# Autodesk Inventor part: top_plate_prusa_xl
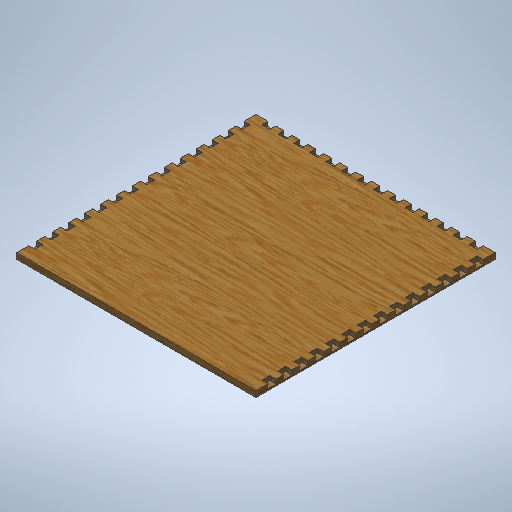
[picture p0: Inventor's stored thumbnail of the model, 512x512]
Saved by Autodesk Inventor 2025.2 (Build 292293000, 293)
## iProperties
Created: 2024-11
Part Number: top_plate_prusa_xl
Material: Plywood, Finish
Document SubType Name: Modeling
Designer: BennF
Density: 0.552 g/cm^3
Appearance: Plywood - New
Author: BennF
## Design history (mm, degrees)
sketch "Sketch2"
  geometry: L1 (-360, 360)-(360, 360); L2 (360, 360)-(360, -360); L3 (360, -360)-(-360, -360); L4 (-360, -360)-(-360, 360); 3 further points
  constraints: 8 end point, 2 midpoint, 2 parallel, 1 horizontal, 1 horizontal alignment, 1 perpendicular, 1 vertical alignment
  dimensions: "d0" = 720 distance of L1.start L1.end (= prusa_xl_width); "d1" = 720 distance of L3.end L1.start (= prusa_xl_depth)
extrude "base_material" new body sketch "Sketch2" distance "d2" = 18 (= thickness); taper "d3" = 0 deg
sketch "Sketch3"
  geometry: L1 (-324, 360)-(-324, 341.8); L2 (-324, 341.8)-(-300, 341.8); L3 (-300, 341.8)-(-300, 360); L4 (-276, 360)-(-276, 341.8); L5 (-276, 341.8)-(-252, 341.8); L6 (-252, 341.8)-(-252, 360); L7 (-228, 360)-(-228, 341.8); L8 (-228, 341.8)-(-204, 341.8); L9 (-204, 341.8)-(-204, 360); L10 (-180, 360)-(-180, 341.8); L11 (-180, 341.8)-(-156, 341.8); L12 (-156, 341.8)-(-156, 360); L13 (-132, 360)-(-132, 341.8); L14 (-132, 341.8)-(-108, 341.8); L15 (-108, 341.8)-(-108, 360); L16 (-84, 360)-(-84, 341.8); L17 (-84, 341.8)-(-60, 341.8); L18 (-60, 341.8)-(-60, 360); L19 (-36, 360)-(-36, 341.8); L20 (-36, 341.8)-(-12, 341.8); L21 (-12, 341.8)-(-12, 360); L22 (12, 360)-(12, 341.8); L23 (12, 341.8)-(36, 341.8); L24 (36, 341.8)-(36, 360); L25 (60, 360)-(60, 341.8); L26 (60, 341.8)-(84, 341.8); L27 (84, 341.8)-(84, 360); L28 (108, 360)-(108, 341.8); L29 (108, 341.8)-(132, 341.8); L30 (132, 341.8)-(132, 360); L31 (156, 360)-(156, 341.8); L32 (156, 341.8)-(180, 341.8); L33 (180, 341.8)-(180, 360); L34 (204, 360)-(204, 341.8); L35 (204, 341.8)-(228, 341.8); L36 (228, 341.8)-(228, 360); L37 (252, 360)-(252, 341.8); L38 (252, 341.8)-(276, 341.8); L39 (276, 341.8)-(276, 360); L40 (300, 360)-(300, 341.8); L41 (300, 341.8)-(324, 341.8); L42 (324, 341.8)-(324, 360); L43 (-360, -324)-(-341.8, -324); L44 (-341.8, -324)-(-341.8, -300); L45 (-341.8, -300)-(-360, -300); L46 (-341.8, -252)-(-360, -252); L47 (-341.8, -276)-(-341.8, -252); L48 (-360, -276)-(-341.8, -276); L49 (-341.8, -204)-(-360, -204); L50 (-341.8, -228)-(-341.8, -204); L51 (-360, -228)-(-341.8, -228); L52 (-341.8, -156)-(-360, -156); L53 (-341.8, -180)-(-341.8, -156); L54 (-360, -180)-(-341.8, -180); L55 (-341.8, -108)-(-360, -108); L56 (-341.8, -132)-(-341.8, -108); L57 (-360, -132)-(-341.8, -132); L58 (-341.8, -60)-(-360, -60); L59 (-341.8, -84)-(-341.8, -60); L60 (-360, -84)-(-341.8, -84); L61 (-341.8, -12)-(-360, -12); L62 (-341.8, -36)-(-341.8, -12); L63 (-360, -36)-(-341.8, -36); L64 (-341.8, 36)-(-360, 36)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; 81 further points
  constraints: 252 end point, 104 vertical alignment, 78 parallel, 53 horizontal alignment, 39 collinear, 6 perpendicular, 2 equal length, 2 horizontal, 1 vertical, 9 other
  dimensions: "d4" = 24 distance of L1.end L2.end (= finger_width); "d5" = 18.2 distance of L2.end L3.end (derived); "d8" = 48 distance of L1.start L4.start (= finger_distance); "d13" = 24 distance of L43.end L44.end (= finger_width); "d14" = 18.2 distance of L44.end L45.end (derived); "d17" = 48 distance of L45.end L46.end (= finger_distance); "d48" = 36 distance between parallel lines of L85 L43 (derived); "d49" = 36 dimension on L1 (derived); "d52" = 48 distance of L86.start L89.start (derived)
extrude "joints" cut sketch "Sketch3" distance "d22" = 13.5 (derived); taper "d23" = 0 deg
sketch "Sketch4" dims "d24" = 6 (= dogbone_diameter)
  geometry: L1 (-341.8, -228)-(-360, -228) reference; L2 (-360, -228)-(-360, -252) reference; L3 (-360, -252)-(-341.8, -252) reference; L4 (-341.8, -252)-(-341.8, -276) reference; L5 (-341.8, -276)-(-360, -276) reference; L6 (-360, -276)-(-360, -300) reference; L7 (-360, -300)-(-341.8, -300) reference; L8 (-341.8, -300)-(-341.8, -324) reference; L9 (-341.8, -324)-(-360, -324) reference; L10 (-360, -324)-(-360, -360) reference; L11 (-360, -360)-(360, -360) reference; L12 (360, -360)-(360, -324) reference; L13 (360, 360)-(324, 360) reference; L14 (132, 360)-(132, 341.8) reference; L15 (132, 341.8)-(108, 341.8) reference; L16 (108, 341.8)-(108, 360) reference; L17 (108, 360)-(84, 360) reference; L18 (84, 360)-(84, 341.8) reference; L19 (84, 341.8)-(60, 341.8) reference; L20 (60, 341.8)-(60, 360) reference; L21 (60, 360)-(36, 360) reference; L22 (36, 360)-(36, 341.8) reference; L23 (36, 341.8)-(12, 341.8) reference; L24 (12, 341.8)-(12, 360) reference; L25 (12, 360)-(-12, 360) reference; L26 (-12, 360)-(-12, 341.8) reference; L27 (-12, 341.8)-(-36, 341.8) reference; L28 (-36, 341.8)-(-36, 360) reference; L29 (-36, 360)-(-60, 360) reference; L30 (-60, 360)-(-60, 341.8) reference; L31 (-60, 341.8)-(-84, 341.8) reference; L32 (-84, 341.8)-(-84, 360) reference; L33 (-84, 360)-(-108, 360) reference; L34 (-108, 360)-(-108, 341.8) reference; L35 (-108, 341.8)-(-132, 341.8) reference; L36 (-132, 341.8)-(-132, 360) reference; L37 (-132, 360)-(-156, 360) reference; L38 (-156, 360)-(-156, 341.8) reference; L39 (-156, 341.8)-(-180, 341.8) reference; L40 (-180, 341.8)-(-180, 360) reference; L41 (-180, 360)-(-204, 360) reference; L42 (-204, 360)-(-204, 341.8) reference; L43 (-204, 341.8)-(-228, 341.8) reference; L44 (-228, 341.8)-(-228, 360) reference; L45 (-228, 360)-(-252, 360) reference; L46 (-252, 360)-(-252, 341.8) reference; L47 (-252, 341.8)-(-276, 341.8) reference; L48 (-276, 341.8)-(-276, 360) reference; L49 (-276, 360)-(-300, 360) reference; L50 (-300, 360)-(-300, 341.8) reference; L51 (-300, 341.8)-(-324, 341.8) reference; L52 (-324, 341.8)-(-324, 360) reference; L53 (-324, 360)-(-360, 360) reference; L54 (-360, 360)-(-360, 324) reference; L55 (-360, 324)-(-341.8, 324) reference; L56 (-341.8, 324)-(-341.8, 300) reference; L57 (-341.8, 300)-(-360, 300) reference; L58 (-360, 300)-(-360, 276) reference; L59 (-360, 276)-(-341.8, 276) reference; L60 (-341.8, 276)-(-341.8, 252) reference; L61 (-341.8, 252)-(-360, 252) reference; L62 (-360, 252)-(-360, 228) reference; L63 (-360, 228)-(-341.8, 228) reference; L64 (-341.8, 228)-(-341.8, 204) reference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; 140 further points
  constraints: 116 end point, 58 point on line, 54 vertical, 27 horizontal, 3 midpoint, 3 perpendicular, 2 horizontal alignment, 1 vertical alignment, 512 other
  dimensions: "d27" = 48 distance of L7.end L104.start (= finger_distance); "d34" = 48 distance of L50.end L133.end (= finger_distance); "d59" = 48 distance of point (343.921, -302.121) point (343.921, -254.121) (derived)
extrude "dogbones" cut sketch "Sketch4" distance "d39" = 13.5 (derived); taper "d40" = 0 deg
body "Solid1"
node "Sketch Rectangular Pattern1" dims "d8" = 48 (= finger_distance), "d11" = 10
node "Sketch Rectangular Pattern2" dims "d17" = 48 (= finger_distance), "d20" = 10
node "Projected Loop1"
node "Sketch Rectangular Pattern3" dims "d27" = 48 (= finger_distance), "d30" = 10
node "Sketch Rectangular Pattern4" dims "d34" = 48 (= finger_distance), "d37" = 10
node "Sketch Rectangular Pattern6" dims "d52" = 48 (derived), "d55" = 10
node "Sketch Rectangular Pattern7" dims "d59" = 48 (derived), "d62" = 10
other parameters: "thickness" = 18 [user parameter; used in 1 equation term], "prusa_xl_depth" = 720 [user parameter; used in 1 equation term], "finger_depth" = 18 [user parameter], "prusa_xl_width" = 720 [user parameter; used in 1 equation term], "finger_width" = 24 [user parameter; used in 2 equation terms], "dogbone_diameter" = 6 [user parameter; used in 1 equation term], "finger_distance" = 48 [user parameter; used in 4 equation terms], "mill_bit" = 6 [user parameter], "dogbone_angle" = 45 deg [user parameter], "prusa_xl_depth_finger_distance" = 36 [user parameter], "prusa_xl_height" = 1005 [user parameter], "prusa_xl_height_finger_distance" = 34.5 [user parameter], "prusa_xl_width_finger_distance" = 36 [user parameter], "prusa_xl_shelf_depth" = 702 [user parameter], "prusa_xl_shelf_width" = 684 [user parameter], "box_clearence_1" = 9.33333 [user parameter], "box_height_1" = 435 [user parameter], "box_height_2" = 235 [user parameter], "hidden_depth" = 4.5 [user parameter], "connection_clearence" = 0.2 [user parameter], "sla_width" = 1296 [user parameter], "back_distance" = 5 [user parameter], "back_connection_depth" = 5 [user parameter], "storage_width_2" = 322 [user parameter], "box_clearence_2" = 24.33333 [user parameter], "shelf_depth_finger_distance" = 39 [user parameter], "connection_back_clearence" = 0 [user parameter], "thickness_back" = 6 [user parameter], "finger_depth_middle" = 8 [user parameter], "box_height_3" = 285 [user parameter], "bowden_tube_diameter" = 4 [user parameter], "connector_width_offset" = 105 [user parameter], "connector_width" = 26 [user parameter], "connector_depth" = 16 [user parameter]
